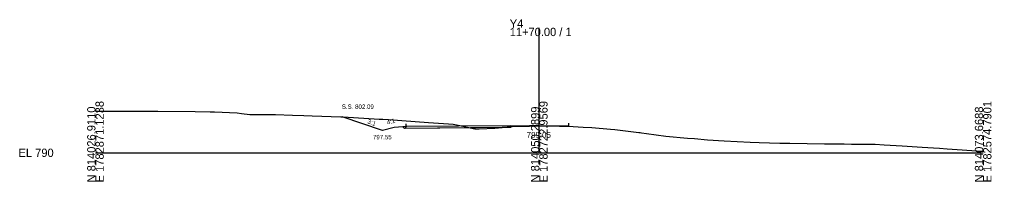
# Model space of a CAD drawing. Extents: x -26 to 3903, y -10 to 9562.
# Drawn here: x 2274.3 to 2602.8, y -9.7 to 45 of the extents above; entities that cross this region are included whole.
import ezdxf

# ---------------------------------------------------------------- set-up
doc = ezdxf.new("R2010")
doc.units = 0
for name, color, linetype in [('Exist Cross Section Cell', 7, 'Continuous'), ('Exist XS Center Line Elevation Label', 7, 'Continuous'), ('Exist XS Ground Line', 7, 'Continuous'), ('Prop XS Ditch Slope Text', 7, 'Continuous'), ('Prop XS Ditch Standard Text', 7, 'Continuous'), ('Prop XS Dump Level', 7, 'Continuous'), ('Prop XS Earthwork Shape', 7, 'Continuous'), ('Prop XS EOT Tick Mark', 7, 'Continuous'), ('Prop XS Finish Grade', 7, 'Continuous'), ('Prop XS Finish Grade Earthwork', 7, 'Continuous'), ('Prop XS Finish Grade Pavement', 7, 'Continuous'), ('Prop XS Pvmt Edge Slope', 7, 'Continuous'), ('Prop XS Side Slope Text', 7, 'Continuous'), ('Prop XS SS Elevation Text', 7, 'Continuous'), ('Prop XS Subgrade Earthwork', 7, 'Continuous')]:
    doc.layers.add(name, color=color, linetype=linetype)

msp = doc.modelspace()

# ---------------------------------------------------------------- linework, layer by layer
at = {"layer": 'Exist Cross Section Cell'}
for p, q in [((2450, 0), (2450, 42.18)), ((2300, 0), (2450, 0)), ((2450, 0), (2600, 0))]:
    msp.add_line(p, q, dxfattribs=at)
at = {"layer": 'Exist XS Ground Line'}
for p, q in [((2300, 14.05), (2303.71, 14.04)), ((2303.71, 14.04), (2305.9, 14.06)), ((2305.9, 14.06), (2308.79, 14.05)), ((2308.79, 14.05), (2321.08, 14.02)), ((2321.08, 14.02), (2333.66, 13.89)), ((2333.66, 13.89), (2338.73, 13.83)), ((2338.73, 13.83), (2340.26, 13.77)), ((2340.26, 13.77), (2347.92, 13.44)), ((2347.92, 13.44), (2349.35, 13.27)), ((2349.35, 13.27), (2352.13, 12.95)), ((2352.13, 12.95), (2354.9, 12.97)), ((2354.9, 12.97), (2360.88, 12.94)), ((2360.88, 12.94), (2366.55, 12.72)), ((2366.55, 12.72), (2370.39, 12.57)), ((2370.39, 12.57), (2373.23, 12.46)), ((2373.23, 12.46), (2382.93, 12.11)), ((2382.93, 12.11), (2383.69, 12.08)), ((2383.69, 12.08), (2395.83, 11.4)), ((2395.83, 11.4), (2397.14, 11.32)), ((2397.14, 11.32), (2399.05, 11.2)), ((2399.05, 11.2), (2412.56, 10.26)), ((2412.56, 10.26), (2419.26, 9.78)), ((2419.26, 9.78), (2420.88, 9.64)), ((2420.88, 9.64), (2422.59, 9.27)), ((2422.59, 9.27), (2428.19, 8.1)), ((2428.19, 8.1), (2429.72, 8.12)), ((2429.72, 8.12), (2435, 8.33)), ((2435, 8.33), (2437.47, 8.5)), ((2437.47, 8.5), (2438.42, 8.62)), ((2438.42, 8.62), (2440.37, 8.98)), ((2440.37, 8.98), (2446.68, 9.03)), ((2446.68, 9.03), (2450.05, 9.05)), ((2450.05, 9.05), (2456.86, 8.94)), ((2456.86, 8.94), (2460.02, 8.93)), ((2460.02, 8.93), (2461.49, 8.83)), ((2461.49, 8.83), (2464.78, 8.65)), ((2464.78, 8.65), (2467.73, 8.53)), ((2467.73, 8.53), (2474.09, 7.95)), ((2474.09, 7.95), (2475.5, 7.84)), ((2475.5, 7.84), (2483.69, 6.89)), ((2483.69, 6.89), (2484.06, 6.84)), ((2484.06, 6.84), (2484.49, 6.78)), ((2484.49, 6.78), (2486.23, 6.53)), ((2486.23, 6.53), (2492.8, 5.59)), ((2492.8, 5.59), (2500.13, 4.95)), ((2500.13, 4.95), (2502.41, 4.77)), ((2502.41, 4.77), (2506.84, 4.42)), ((2506.84, 4.42), (2512.48, 4.03)), ((2512.48, 4.03), (2521.22, 3.56)), ((2521.22, 3.56), (2524.28, 3.46)), ((2524.28, 3.46), (2531.28, 3.3)), ((2531.28, 3.3), (2534.71, 3.22)), ((2534.71, 3.22), (2546.33, 3.04)), ((2546.33, 3.04), (2548.12, 3)), ((2548.12, 3), (2549.95, 3.05)), ((2549.95, 3.05), (2550.64, 3.01)), ((2550.64, 3.01), (2552.99, 2.99)), ((2552.99, 2.99), (2555.55, 2.91)), ((2555.55, 2.91), (2562.1, 2.89)), ((2562.1, 2.89), (2563.54, 2.92)), ((2563.54, 2.92), (2566.55, 2.73)), ((2566.55, 2.73), (2572.62, 2.3)), ((2572.62, 2.3), (2579.37, 1.92)), ((2579.37, 1.92), (2583.25, 1.67)), ((2583.25, 1.67), (2585.24, 1.58)), ((2585.24, 1.58), (2587.79, 1.38)), ((2587.79, 1.38), (2599.59, 0.52)), ((2599.59, 0.52), (2599.94, 0.5)), ((2599.94, 0.5), (2600, 0.5))]:
    msp.add_line(p, q, dxfattribs=at)
at = {"layer": 'Prop XS Earthwork Shape'}
for points in [[(2401, 8.55), (2397, 7.55), (2383.37, 12.09), (2383.69, 12.08), (2395.83, 11.4), (2397.14, 11.32), (2399.05, 11.2), (2412.56, 10.26), (2419.26, 9.78), (2420.88, 9.64), (2422.59, 9.27), (2426.7, 8.41), (2404.41, 8.23), (2403.9, 8.74)], [(2428.19, 8.1), (2429.72, 8.12), (2435, 8.33), (2437.47, 8.5), (2437.49, 8.5), (2426.7, 8.41)], [(2440.37, 8.52), (2437.49, 8.5), (2438.42, 8.62), (2440.37, 8.98)]]:
    msp.add_lwpolyline(points, close=True, dxfattribs=at)
at = {"layer": 'Prop XS EOT Tick Mark'}
for p, q in [((2460.02, 9.05), (2460.02, 10.05)), ((2405, 8.82), (2405, 9.82))]:
    msp.add_line(p, q, dxfattribs=at)
at = {"layer": 'Prop XS Finish Grade'}
msp.add_line((2405, 8.82), (2403.9, 8.74), dxfattribs=at)
at = {"layer": 'Prop XS Finish Grade Earthwork'}
for p, q in [((2397, 7.55), (2383.37, 12.09)), ((2401, 8.55), (2397, 7.55)), ((2403.9, 8.74), (2401, 8.55))]:
    msp.add_line(p, q, dxfattribs=at)
at = {"layer": 'Prop XS Finish Grade Pavement'}
for p, q in [((2440.37, 9.11), (2405, 8.82)), ((2440.37, 9.11), (2446.68, 9.16)), ((2440.37, 9.11), (2440.39, 8.98)), ((2446.68, 9.16), (2450.05, 9.18)), ((2450.06, 9.18), (2456.86, 9.06)), ((2456.86, 9.06), (2460.02, 9.05))]:
    msp.add_line(p, q, dxfattribs=at)
at = {"layer": 'Prop XS Pvmt Edge Slope'}
msp.add_line((2405, 8.82), (2404.41, 8.23), dxfattribs=at)
at = {"layer": 'Prop XS Subgrade Earthwork'}
for p, q in [((2404.41, 8.23), (2403.9, 8.74)), ((2440.37, 8.52), (2404.41, 8.23)), ((2440.37, 8.52), (2440.37, 8.98))]:
    msp.add_line(p, q, dxfattribs=at)

# ---------------------------------------------------------------- texts
at = {"layer": 'Exist Cross Section Cell'}
for s, p in [('Y4', (2440, 42.18)), ('11+70.00 / 1', (2440, 39.38)), ('EL 790', (2274, -1.4))]:
    msp.add_text(s, height=2.8, dxfattribs=at).set_placement(p)
for s, p in [('E 1782871.1238', (2302.8, -10)), ('E 1782722.9569', (2452.8, -10)), ('E 1782574.7901', (2602.8, -10)), ('N 814026.9110', (2300, -10)), ('N 814050.2899', (2450, -10)), ('N 814073.6688', (2600, -10))]:
    msp.add_text(s, height=2.8, rotation=90, dxfattribs=at).set_placement(p)
at = {"layer": 'Exist XS Center Line Elevation Label'}
msp.add_text('799.05', height=2, dxfattribs=at).set_placement((2445.74, 5.05))
at = {"layer": 'Prop XS Ditch Slope Text'}
msp.add_text('4:1', height=1.5, rotation=14.0362, dxfattribs=at).set_placement((2398.64, 9.5))
at = {"layer": 'Prop XS Ditch Standard Text'}
msp.add_text('797.55', height=1.5, dxfattribs=at).set_placement((2393.77, 4.55))
at = {"layer": 'Prop XS Dump Level'}
for s, height, p in [('Case1', 0.04, (2401, 8.51)), ('Eop', 0.3, (2440.37, 8.68))]:
    msp.add_text(s, height=height, dxfattribs=at).set_placement(p)
at = {"layer": 'Prop XS Side Slope Text'}
msp.add_text('3:1', height=1.5, rotation=338.5931, dxfattribs=at).set_placement((2391.78, 10.02))
at = {"layer": 'Prop XS SS Elevation Text'}
msp.add_text('S.S. 802.09', height=1.5, dxfattribs=at).set_placement((2383.25, 14.81))

doc.saveas('drawing.dxf')
